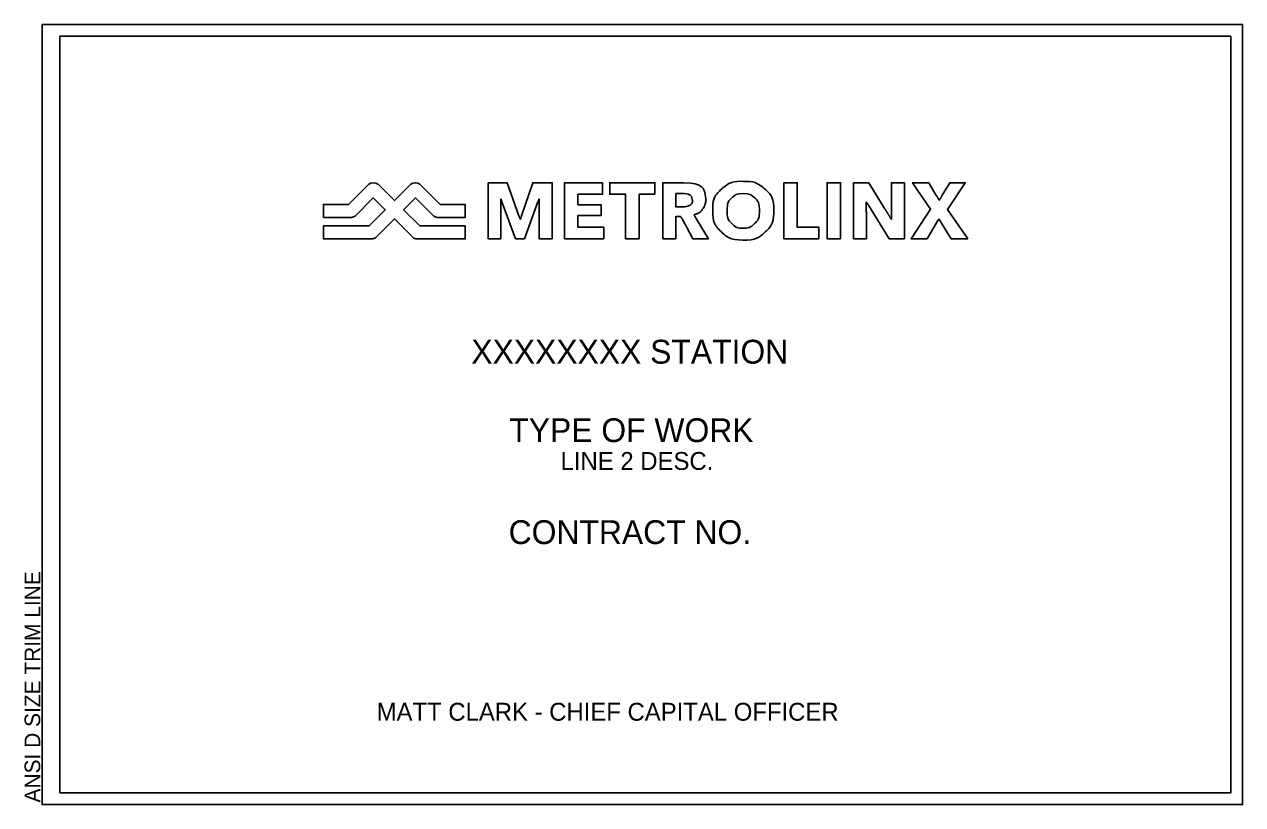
# Model space of a CAD drawing. Extents: x 316474.854 to 316475.672, y 846474.851 to 846475.375.
import ezdxf

# ---------------------------------------------------------------- set-up
doc = ezdxf.new("R2010")
doc.units = 0
for name, color, linetype in [('c_Legend', 7, 'Continuous'), ('c_NO_Print', 7, 'Continuous'), ('CPG_Border', 7, 'Continuous'), ('CPG_Border_Text', 7, 'Continuous')]:
    doc.layers.add(name, color=color, linetype=linetype)

msp = doc.modelspace()

# ---------------------------------------------------------------- linework, layer by layer
at = {"layer": 'c_Legend'}
msp.add_line((316475.07344, 846475.24522), (316475.05448, 846475.24522), dxfattribs=at)
for points in [[(316475.05448, 846475.24522), (316475.05448, 846475.25393), (316475.07129, 846475.25393), (316475.08493, 846475.26752)], [(316475.09116, 846475.26747), (316475.10214, 846475.25659), (316475.11313, 846475.26747)], [(316475.11936, 846475.26752), (316475.133, 846475.25393), (316475.14981, 846475.25393), (316475.14981, 846475.24522), (316475.13085, 846475.24522)], [(316475.17361, 846475.25133), (316475.17361, 846475.2309), (316475.16516, 846475.2309), (316475.16516, 846475.26849), (316475.17787, 846475.26849), (316475.18578, 846475.24629)], [(316475.18758, 846475.24624), (316475.19513, 846475.26849), (316475.20817, 846475.26849), (316475.20817, 846475.2309)], [(316475.24283, 846475.2309), (316475.21652, 846475.2309), (316475.21652, 846475.26849), (316475.24183, 846475.26849), (316475.24183, 846475.26083), (316475.2254, 846475.26083), (316475.2254, 846475.2537), (316475.24096, 846475.2537), (316475.24096, 846475.2465), (316475.2254, 846475.2465), (316475.2254, 846475.2386), (316475.24283, 846475.2386), (316475.24283, 846475.2309)], [(316475.27712, 846475.26083), (316475.26649, 846475.26083), (316475.26649, 846475.2309), (316475.25748, 846475.2309), (316475.25748, 846475.26083), (316475.24682, 846475.26083), (316475.24682, 846475.26849), (316475.27712, 846475.26849), (316475.27712, 846475.26083)], [(316475.29435, 846475.24587), (316475.29129, 846475.24587), (316475.29129, 846475.2309), (316475.28246, 846475.2309), (316475.28246, 846475.26849), (316475.29666, 846475.26849)], [(316475.29129, 846475.26121), (316475.29129, 846475.25235), (316475.29725, 846475.25235)], [(316475.29708, 846475.26121), (316475.29129, 846475.26121)], [(316475.38733, 846475.2309), (316475.36374, 846475.2309), (316475.36374, 846475.26849), (316475.37274, 846475.26849), (316475.37274, 846475.2386), (316475.38733, 846475.2386), (316475.38733, 846475.2309)], [(316475.40188, 846475.2309), (316475.39272, 846475.2309), (316475.39272, 846475.26849), (316475.40188, 846475.26849), (316475.40188, 846475.2309)], [(316475.41918, 846475.24587), (316475.4192, 846475.2309), (316475.41056, 846475.2309), (316475.41056, 846475.26849), (316475.42077, 846475.26849), (316475.43143, 846475.25124)], [(316475.43612, 846475.24587), (316475.43593, 846475.26849), (316475.44474, 846475.26849), (316475.44474, 846475.2309)], [(316475.46724, 846475.24314), (316475.45991, 846475.2309), (316475.44917, 846475.2309), (316475.46231, 846475.25073), (316475.45023, 846475.26849), (316475.46102, 846475.26849), (316475.46614, 846475.26005)], [(316475.47015, 846475.26014), (316475.47511, 846475.26849), (316475.48559, 846475.26849), (316475.47372, 846475.25065), (316475.48723, 846475.2309)], [(316475.08693, 846475.23086), (316475.05448, 846475.23086), (316475.05448, 846475.23956), (316475.08512, 846475.23956), (316475.09599, 846475.25041), (316475.08802, 846475.25831), (316475.07573, 846475.24606)], [(316475.12856, 846475.24606), (316475.11627, 846475.25831), (316475.1083, 846475.25041), (316475.11917, 846475.23956), (316475.14981, 846475.23956), (316475.14981, 846475.23086), (316475.11736, 846475.23086)], [(316475.17434, 846475.25577), (316475.17361, 846475.25776)], [(316475.19861, 846475.25563), (316475.18944, 846475.2309), (316475.18352, 846475.2309), (316475.17434, 846475.25577)], [(316475.20817, 846475.2309), (316475.1994, 846475.2309), (316475.19937, 846475.25323)], [(316475.1994, 846475.25776), (316475.1994, 846475.25776)], [(316475.41904, 846475.25558), (316475.41904, 846475.25558)], [(316475.44474, 846475.2309), (316475.43442, 846475.2309), (316475.42056, 846475.2535)], [(316475.46799, 846475.2569), (316475.4682, 846475.2569)], [(316475.11467, 846475.23176), (316475.10214, 846475.24425), (316475.08962, 846475.23176)], [(316475.30438, 846475.24737), (316475.30343, 846475.24702)], [(316475.18679, 846475.24391), (316475.18679, 846475.24391)], [(316475.31311, 846475.2309), (316475.30255, 846475.2309), (316475.2983, 846475.23889)], [(316475.30577, 846475.24297), (316475.31311, 846475.2309)], [(316475.43593, 846475.24389), (316475.43612, 846475.2439)], [(316475.46801, 846475.2441), (316475.46781, 846475.24411)], [(316475.48723, 846475.2309), (316475.4761, 846475.2309), (316475.46856, 846475.24315)]]:
    msp.add_lwpolyline(points, dxfattribs=at)
for centre, radius, start, end in [((316475.08801, 846475.26347), 0.00509, 51.84972, 127.27899), ((316475.11628, 846475.26347), 0.00509, 52.72101, 128.15028), ((316475.07218, 846475.25223), 0.00713, 280.17536, 299.87114), ((316475.13211, 846475.25223), 0.00713, 240.12886, 259.82464), ((316475.08654, 846475.23647), 0.00563, 273.96872, 303.17718), ((316475.11775, 846475.23647), 0.00563, 236.82282, 266.03128)]:
    msp.add_arc(centre, radius, start, end, dxfattribs=at)
for points, degree in [([(316475.33614, 846475.22994), (316475.32764, 846475.23005), (316475.32191, 846475.23519), (316475.31631, 846475.24089), (316475.31595, 846475.24916), (316475.31583, 846475.25868), (316475.32208, 846475.26448), (316475.32808, 846475.26957), (316475.33671, 846475.26949), (316475.3448, 846475.26933), (316475.35051, 846475.26479), (316475.35669, 846475.25938), (316475.35705, 846475.25027), (316475.35699, 846475.24078), (316475.35081, 846475.23497), (316475.34485, 846475.22974), (316475.33614, 846475.22994)], 3), ([(316475.29666, 846475.26849), (316475.30961, 846475.26853), (316475.3112, 846475.25905), (316475.31141, 846475.25575), (316475.31068, 846475.2537), (316475.3101, 846475.25206), (316475.30928, 846475.25089), (316475.30785, 846475.24883), (316475.30618, 846475.2482), (316475.30535, 846475.24759), (316475.30438, 846475.24737)], 3), ([(316475.29725, 846475.25235), (316475.29878, 846475.25251), (316475.30043, 846475.2533), (316475.30269, 846475.25478), (316475.30224, 846475.25808), (316475.30101, 846475.26121), (316475.29708, 846475.26121)], 3), ([(316475.33636, 846475.2614), (316475.33192, 846475.26138), (316475.32929, 846475.25877), (316475.32575, 846475.25571), (316475.32572, 846475.24991), (316475.32558, 846475.24421), (316475.32896, 846475.24105), (316475.33174, 846475.23792), (316475.3364, 846475.23818), (316475.34063, 846475.2379), (316475.34372, 846475.24077), (316475.34729, 846475.24404), (316475.34739, 846475.24968), (316475.34726, 846475.25567), (316475.34354, 846475.25886), (316475.34088, 846475.2613), (316475.33636, 846475.2614)], 3), ([(316475.17361, 846475.25776), (316475.17361, 846475.2555), (316475.17361, 846475.25133)], 2), ([(316475.17434, 846475.25577), (316475.17361, 846475.25695), (316475.17434, 846475.25577)], 2), ([(316475.1994, 846475.25776), (316475.19897, 846475.25661), (316475.19861, 846475.25563)], 2), ([(316475.19937, 846475.25323), (316475.19937, 846475.25684), (316475.1994, 846475.25776)], 2), ([(316475.42056, 846475.2535), (316475.41962, 846475.25508), (316475.41904, 846475.25558)], 2), ([(316475.41904, 846475.25558), (316475.41904, 846475.25446), (316475.41918, 846475.24587)], 2), ([(316475.46614, 846475.26005), (316475.46728, 846475.25818), (316475.46799, 846475.2569)], 2), ([(316475.4682, 846475.2569), (316475.4691, 846475.25827), (316475.47015, 846475.26014)], 2), ([(316475.18578, 846475.24629), (316475.18631, 846475.24491), (316475.18679, 846475.24391)], 2), ([(316475.18679, 846475.24391), (316475.18679, 846475.24391), (316475.18758, 846475.24624)], 2), ([(316475.2983, 846475.23889), (316475.29716, 846475.24103), (316475.29668, 846475.24196), (316475.29601, 846475.24317), (316475.29567, 846475.24378), (316475.29524, 846475.24467), (316475.29435, 846475.24587), (316475.29469, 846475.2457), (316475.29435, 846475.24587)], 3), ([(316475.30343, 846475.24702), (316475.30343, 846475.24702), (316475.30369, 846475.24643), (316475.30381, 846475.24618), (316475.30416, 846475.24559), (316475.30456, 846475.24496), (316475.30494, 846475.24428), (316475.3051, 846475.24401), (316475.30577, 846475.24297)], 3), ([(316475.43143, 846475.25124), (316475.43359, 846475.24781), (316475.43593, 846475.24389)], 2), ([(316475.43612, 846475.2439), (316475.43613, 846475.24489), (316475.43612, 846475.24587)], 2), ([(316475.46781, 846475.24411), (316475.46745, 846475.24356), (316475.46724, 846475.24314)], 2), ([(316475.46856, 846475.24315), (316475.4682, 846475.24367), (316475.46801, 846475.2441)], 2)]:
    msp.add_open_spline(points, degree=degree, dxfattribs=at)
at = {"layer": 'c_NO_Print'}
msp.add_lwpolyline([(316474.86557, 846475.37489), (316475.67187, 846475.37489), (316475.67187, 846474.8509), (316474.86557, 846474.8509)], close=True, dxfattribs=at)
at = {"layer": 'CPG_Border'}
msp.add_lwpolyline([(316475.66387, 846474.8589), (316475.66387, 846475.36689), (316474.87757, 846475.36689), (316474.87757, 846474.8589)], close=True, dxfattribs=at)

# ---------------------------------------------------------------- texts
at = {"layer": 'c_NO_Print'}
msp.add_text('ANSI D SIZE TRIM LINE', height=0.0105059, rotation=90, dxfattribs=at).set_placement((316474.86431, 846474.85233))
at = {"layer": 'CPG_Border_Text'}
for s, height, p in [('XXXXXXXX STATION', 0.016, (316475.15384, 846475.14707)), ('TYPE OF WORK', 0.016, (316475.17934, 846475.09435)), ('LINE 2 DESC.', 0.012, (316475.2138, 846475.07568)), ('CONTRACT NO.', 0.016, (316475.17891, 846475.02589)), ('MATT CLARK - CHIEF CAPITAL OFFICER', 0.012, (316475.09025, 846474.90727))]:
    msp.add_text(s, height=height, dxfattribs=at).set_placement(p)

doc.saveas('drawing.dxf')
